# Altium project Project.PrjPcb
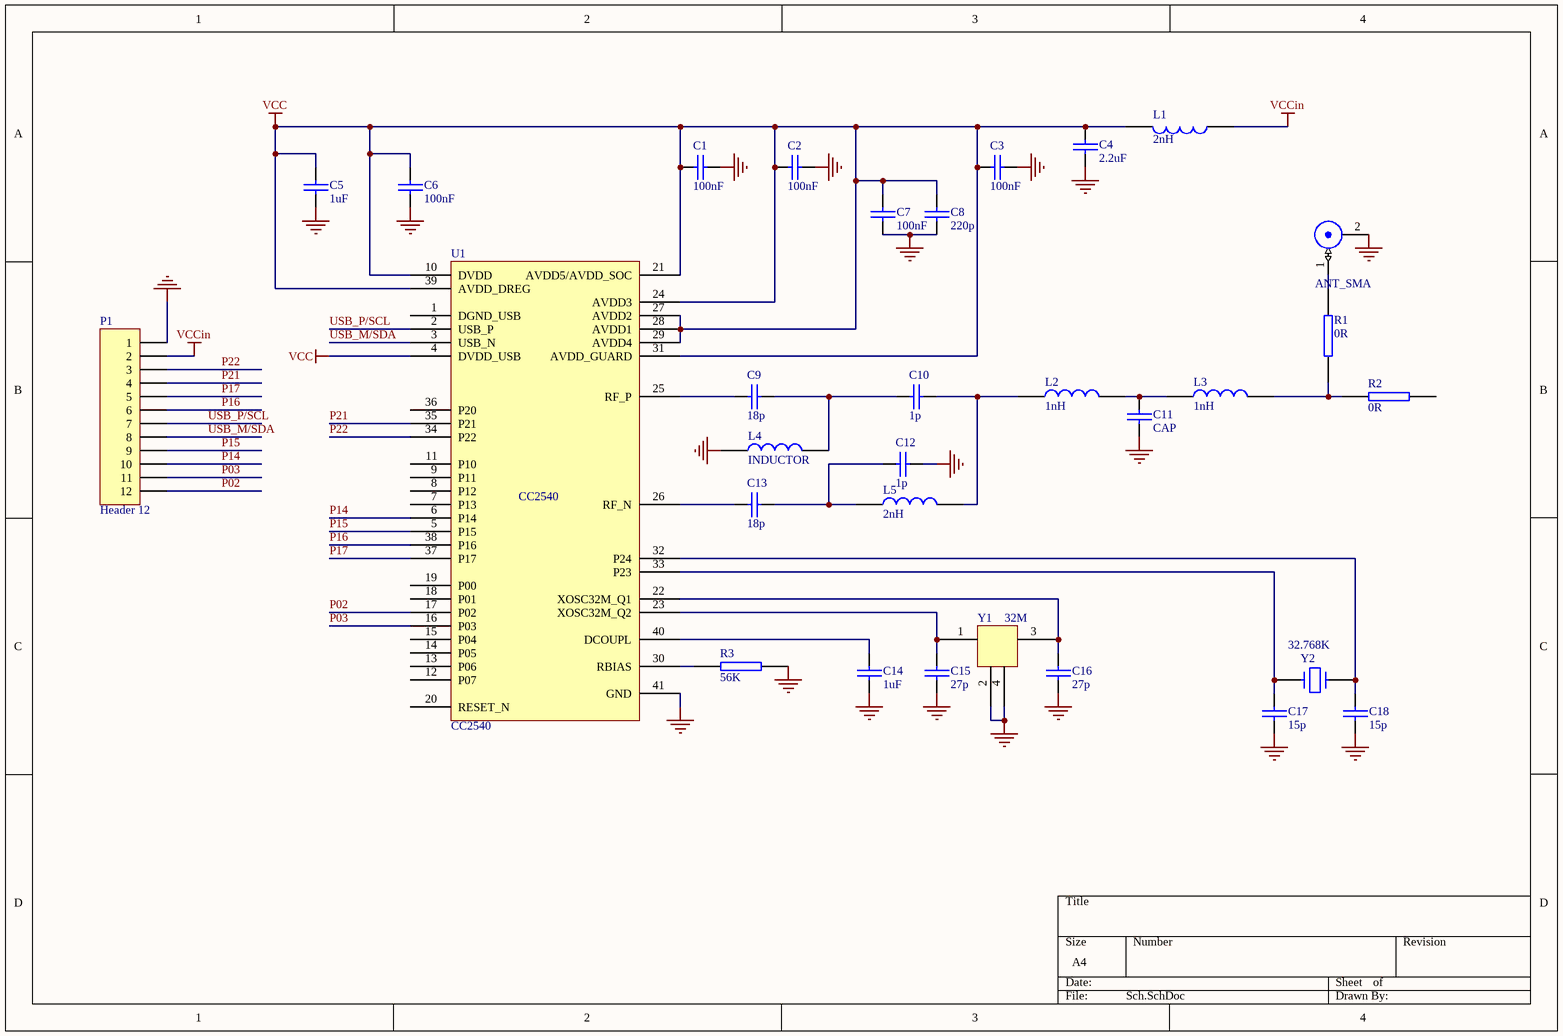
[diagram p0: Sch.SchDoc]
1 sheet, 31 parts. Net scope: global (net labels, ports and power ports of the same name join across sheets).
Board file: pcb.pcbdoc

## Sheet Sch.SchDoc
size A4

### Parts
C1  100nF  [0402_SMALL]
C2  100nF  [0402_SMALL]
C3  100nF  [0402_SMALL]
C4  2.2uF  [0402_SMALL]
C5  1uF  [0402_SMALL]
C6  100nF  [0402_SMALL]
C7  100nF  [0402_SMALL]
C8  220p  [0402_SMALL]
C9  18p  [0402_SMALL]
C10  1p  [0402_SMALL]
C11  CAP  [0402_SMALL]
C12  1p  [0402_SMALL]
C13  18p  [0402_SMALL]
C14  1uF  [0402_SMALL]
C15  27p  [0402_SMALL]
C16  27p  [0402_SMALL]
C17  15p  [0402_SMALL]
C18  15p  [0402_SMALL]
L1  2nH  [0402_SMALL]
L2  1nH  [0402_SMALL]
L3  1nH  [0402_SMALL]
L4  INDUCTOR  [0402_SMALL]
L5  2nH  [0402_SMALL]
P1  Header 12  [M-IDC12M]
R1  0R  [0402_SMALL]
R2  0R  [0402_SMALL]
R3  56K  [0402_SMALL]
U1  CC2540  [CC2530_QFN]
Y1  32M  [CY_3225]
Y2  32.768K  [CRYSTAL_3215]
  ANT_SMA  [SMA_EB]

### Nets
GND: C1.2 C2.2 C3.2 C4.2 C5.2 C6.2 C7.1 C8.1 C11.2 C12.2 C14.2 C15.2 C16.2 C17.2 C18.2 L4.1 P1.1 R3.2 U1.41(GND) Y1.2 Y1.4 .2
VCC: C1.1 C2.1 C3.1 C4.1 C5.1 C6.1 C7.2 C8.2 L1.2 U1.4(DVDD_USB) U1.10(DVDD) U1.21(AVDD5/AVDD_SOC) U1.24(AVDD3) U1.27(AVDD2) U1.28(AVDD1) U1.29(AVDD4) U1.31(AVDD_GUARD) U1.39(AVDD_DREG)
VCCin: L1.1 P1.2
P02: P1.12 U1.17(P02)
P03: P1.11 U1.16(P03)
P14: P1.10 U1.6(P14)
P15: P1.9 U1.5(P15)
P16: P1.6 U1.38(P16)
P17: P1.5 U1.37(P17)
P21: P1.4 U1.35(P21)
P22: P1.3 U1.34(P22)
USB_M/SDA: P1.8 U1.3(USB_N)
USB_P/SCL: P1.7 U1.2(USB_P)
NetC9_1: C9.1 U1.25(RF_P)
NetC9_2: C9.2 C10.1 L4.2
NetC10_2: C10.2 L2.1 L5.2
NetC11_1: C11.1 L2.2 L3.1
NetC12_1: C12.1 C13.2 L5.1
NetC13_1: C13.1 U1.26(RF_N)
NetC14_1: C14.1 U1.40(DCOUPL)
NetC15_1: C15.1 U1.23(XOSC32M_Q2) Y1.1
NetC16_1: C16.1 U1.22(XOSC32M_Q1) Y1.3
NetC17_1: C17.1 U1.33(P23) Y2.1
NetC18_1: C18.1 U1.32(P24) Y2.2
NetL3_2: L3.2 R1.1 R2.2
NetR1_2: R1.2 .1
NetR3_1: R3.1 U1.30(RBIAS)

Not connected (* = marked no-connect by the designer): R2 1; U1 1(DGND_USB) 7(P13) 8(P12) 9(P11) 11(P10) 12(P07) 13(P06) 14(P05) 15(P04) 18(P01) 19(P00) 20(RESET_N) 36(P20)

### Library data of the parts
C1-C18 = CAP: Capacitor
L1-L3 L5 = INDUCTOR
P1 = Header 12: Header, 12-Pin
R1-R3 = RES2
Y1 = CY_3225
Y2 = CRYSTAL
